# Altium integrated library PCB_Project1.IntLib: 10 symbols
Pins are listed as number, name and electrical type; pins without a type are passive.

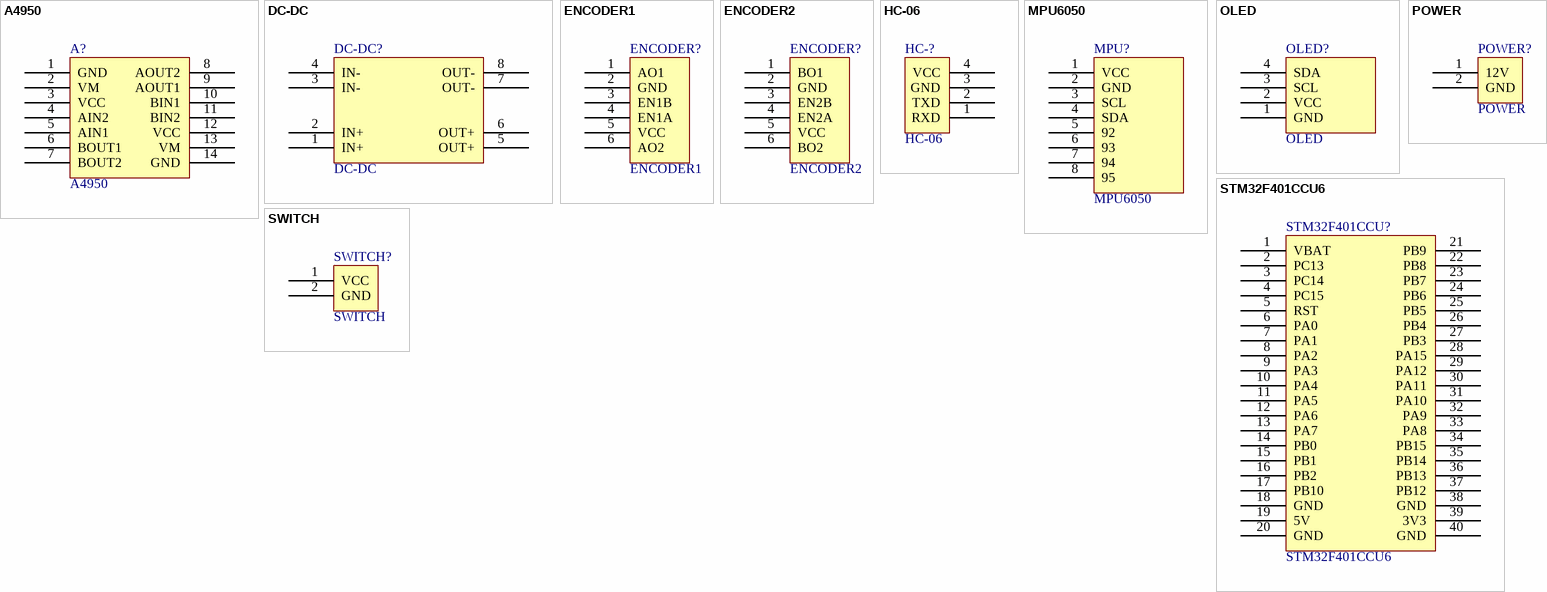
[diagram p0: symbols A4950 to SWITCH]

## A4950
designator A?
footprint A4950
pins: 1 GND, 2 VM, 3 VCC, 4 AIN2, 5 AIN1, 6 BOUT1, 7 BOUT2, 8 AOUT2, 9 AOUT1, 10 BIN1, 11 BIN2, 12 VCC, 13 VM, 14 GND

## DC-DC
designator DC-DC?
footprint DC-DC
pins: 1 IN+, 2 IN+, 3 IN-, 4 IN-, 5 OUT+, 6 OUT+, 7 OUT-, 8 OUT-

## ENCODER1
designator ENCODER?
footprint ENCODER1
pins: 1 AO1, 2 GND, 3 EN1B, 4 EN1A, 5 VCC, 6 AO2

## ENCODER2
designator ENCODER?
footprint ENCODER2
pins: 1 BO1, 2 GND, 3 EN2B, 4 EN2A, 5 VCC, 6 BO2

## HC-06
designator HC-?
footprint HC-06
pins: 1 RXD, 2 TXD, 3 GND, 4 VCC

## MPU6050
designator MPU?
footprint MPU6050
pins: 1 VCC, 2 GND, 3 SCL, 4 SDA, 5 92, 6 93, 7 94, 8 95

## OLED
designator OLED?
footprint OLED
pins: 1 GND, 2 VCC, 3 SCL, 4 SDA

## POWER
designator POWER?
footprint POWER
pins: 1 12V, 2 GND

## STM32F401CCU6
designator STM32F401CCU?
footprint STM32F401CCU6
pins: 1 VBAT, 2 PC13, 3 PC14, 4 PC15, 5 RST, 6 PA0, 7 PA1, 8 PA2, 9 PA3, 10 PA4, 11 PA5, 12 PA6, 13 PA7, 14 PB0, 15 PB1, 16 PB2, 17 PB10, 18 GND, 19 5V, 20 GND, 21 PB9, 22 PB8, 23 PB7, 24 PB6, 25 PB5, 26 PB4, 27 PB3, 28 PA15, 29 PA12, 30 PA11, 31 PA10, 32 PA9, 33 PA8, 34 PB15, 35 PB14, 36 PB13, 37 PB12, 38 GND, 39 3V3, 40 GND

## SWITCH
designator SWITCH?
footprint SIWITCH
footprint SIWITCH
pins: 1 VCC, 2 GND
